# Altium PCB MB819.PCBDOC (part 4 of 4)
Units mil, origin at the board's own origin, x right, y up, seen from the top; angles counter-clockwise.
Board outline 4505 x 6805 mil, 4 copper layers (TopLayer, MidLayer1, GND, BottomLayer), stack 69.6 mil thick; 336 components, 282 nets, 1318 pads, 584 vias.
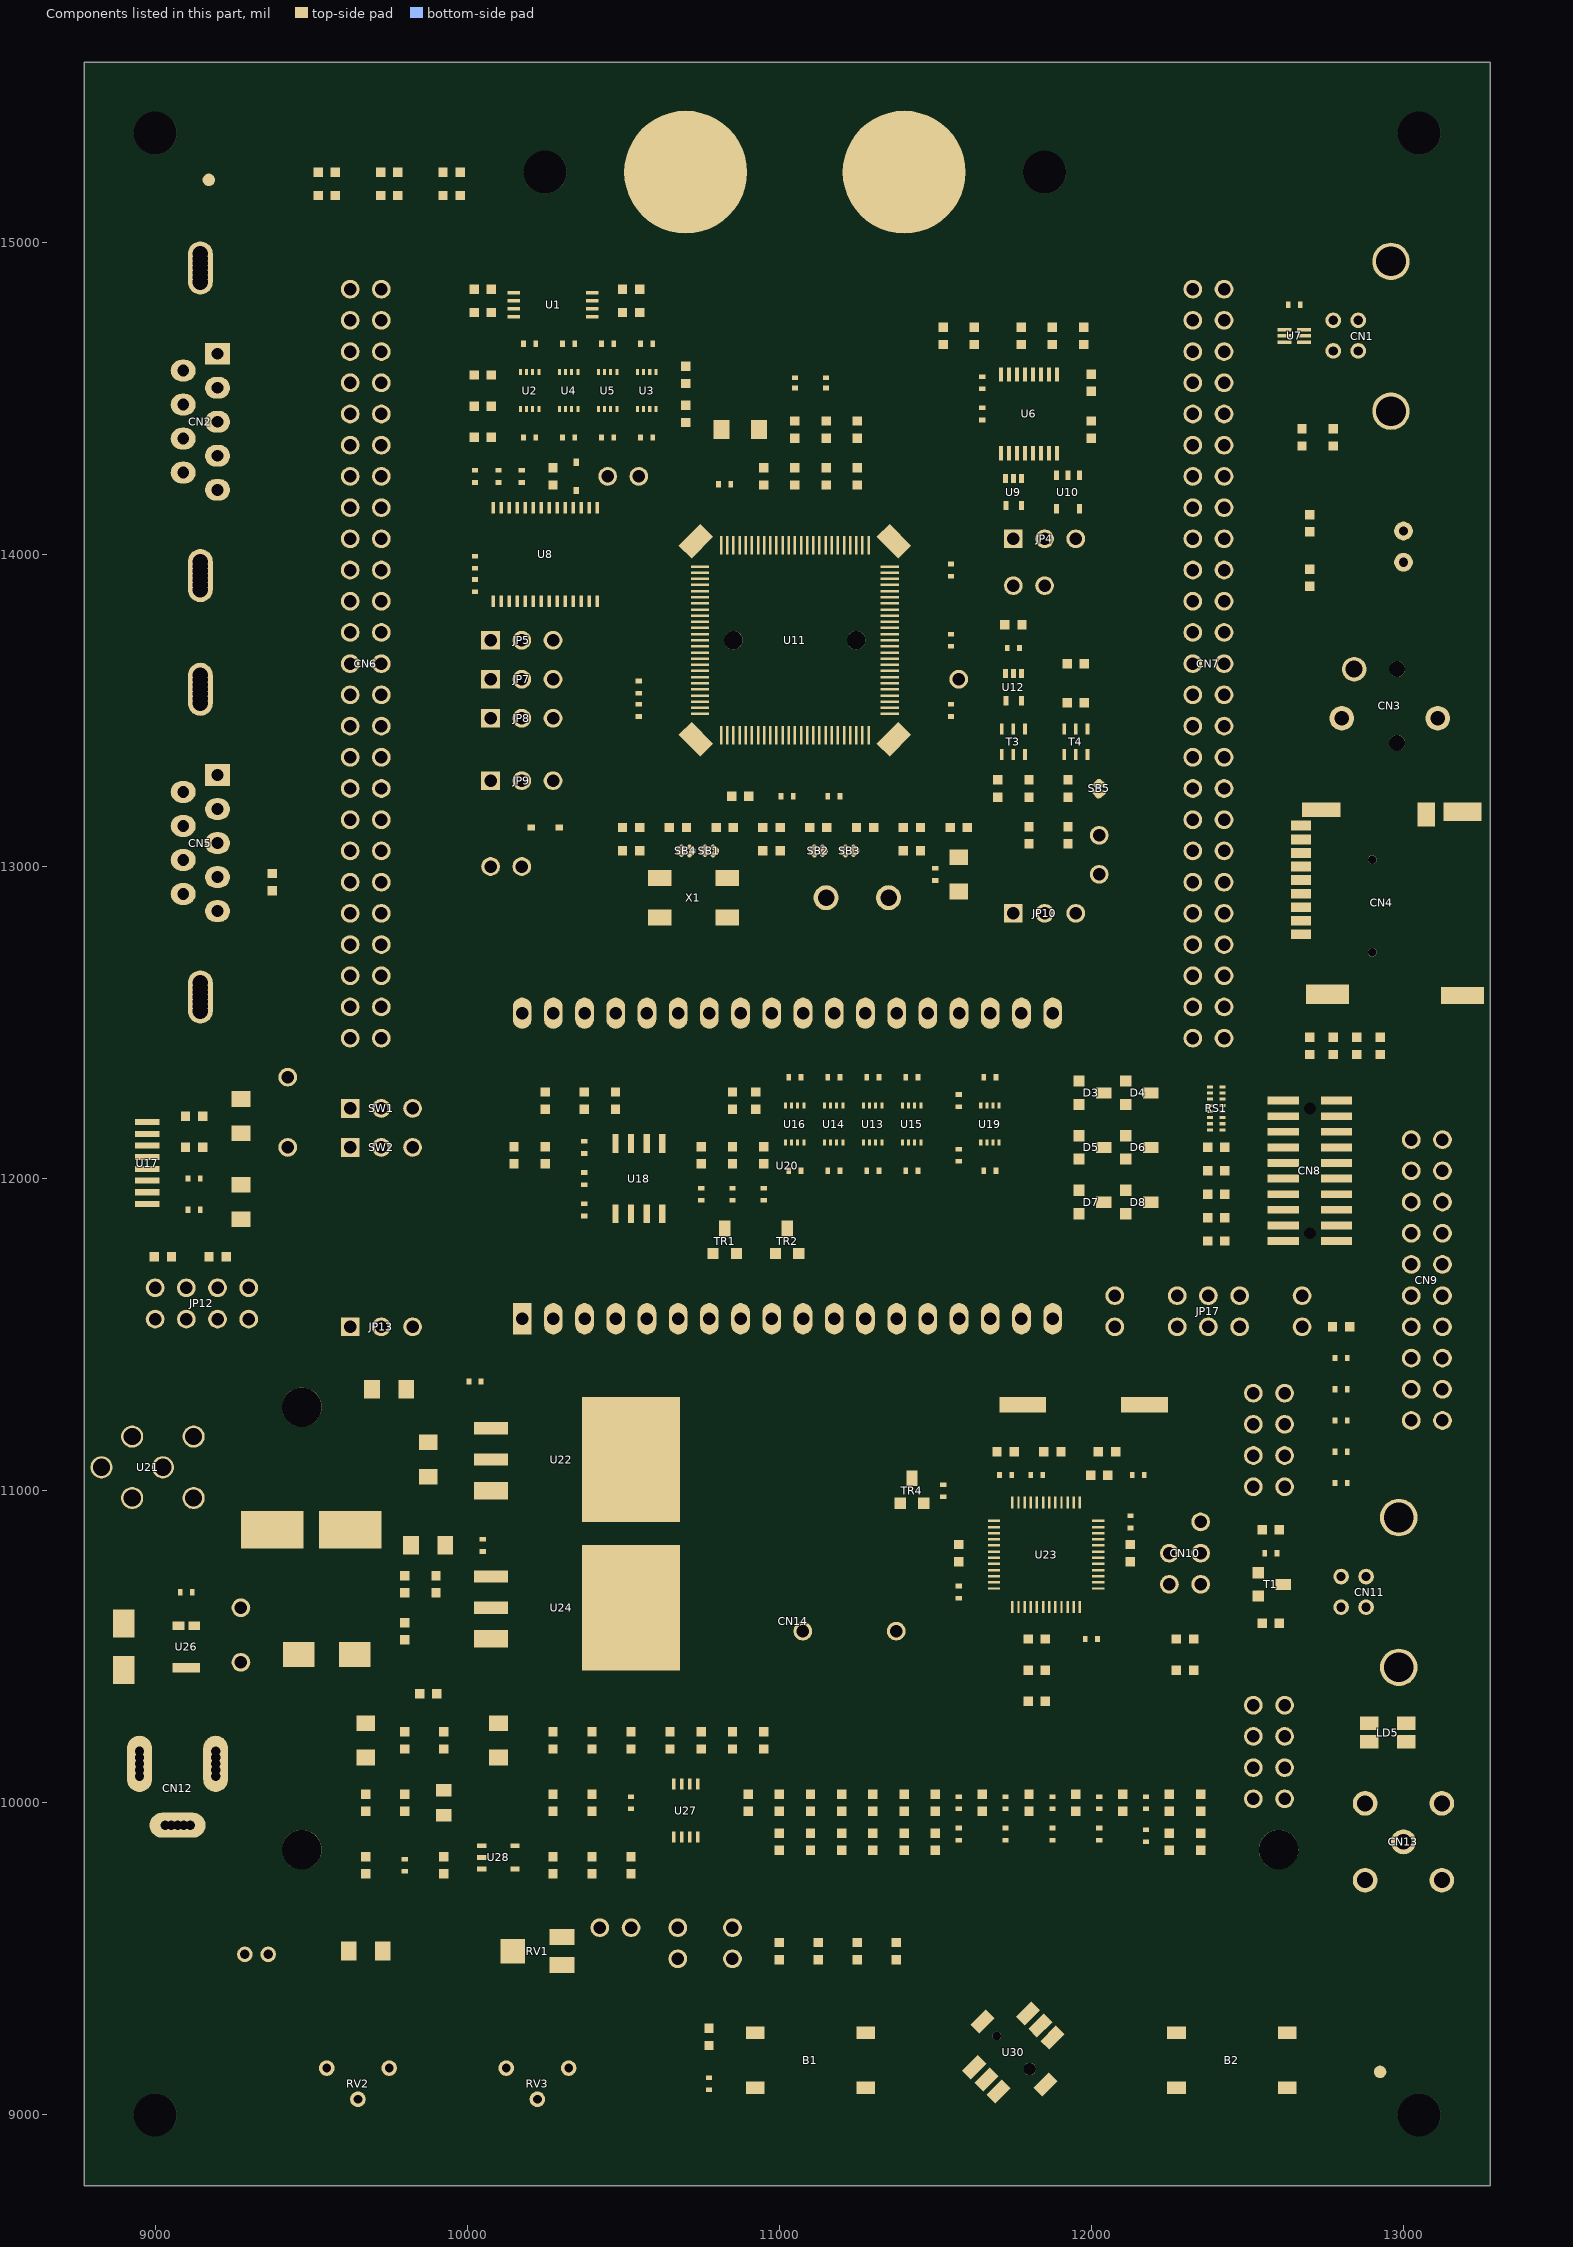
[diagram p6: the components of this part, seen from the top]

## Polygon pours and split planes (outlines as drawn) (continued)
D5V on BottomLayer (hatched 90Degree grid 10 track 10, remove dead copper): 9575,12550 9800,12550 9800,12700 10125,12700 10125,12465 9990,12465 9910,12385 9655,12385 9630,12410 9576.31,12410 9576.31,12550
GND on BottomLayer (hatched 90Degree grid 15 track 10, remove dead copper): 8775,8775 13275,8775 13275,15575 8775,15575

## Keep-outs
KeepOutLayer:
  lines w4: 12025,15125 12150,15125 ; 12025,15250 12150,15250 ; 12025,15375 12150,15375 ; 12275,15125 12275,15250 12275,15375 ; 12400,15125 12400,15250 12400,15375 ; 12525,15125 12525,15250 12525,15375 ; 12775,15250 12650,15250 ; 12150,15125 12150,15250 ; 12150,15125 12650,15125 ; 12150,15250 12650,15250 ; 12150,15250 12150,15375 ; 12150,15375 12650,15375 ; 12650,15125 12650,15250 ; 12650,15125 12775,15125 12775,15375 12650,15375 ; 12650,15250 12650,15375
  lines w5: 12025,15125 12025,15375 ; 8775,8775 8775,10233.87 8775,15575 13275,15575 13275,13155 ccw(c14448.78,12905.51) 13275,12656.01 13275,8775 8775,8775

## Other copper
TopLayer:
  text "1" at 12200,15275 h50
  text "B" at 12190,15165 h50
MidLayer1:
  text "2" at 12320,15275 h50
  text "B" at 12320,15165 h50
BottomLayer:
  text "4" at 12610,15275 h50
  text "B" at 12610,15165 h50
GND (plane layer: these items are gaps in the copper):
  rectangle: 12525,15100 12795,15400
  rectangle: 12400,15100 12525,15125
  rectangle: 12400,15375 12525,15400
  region: 12000,15400 12000,15100 12400,15100 12400,15400
  lines w4: 12025,15125 12150,15125 ; 12025,15250 12150,15250 ; 12025,15375 12150,15375 ; 12150,15255 12150,15250 ; 12275,15125 12275,15250 ; 12275,15255 12275,15375 ; 12400,15125 12400,15250 12400,15375 ; 12525,15125 12525,15250 12525,15375 ; 12150,15125 12650,15125 12650,15250 ; 12150,15125 12150,15250 ; 12150,15250 12650,15250 ; 12150,15250 12150,15375 ; 12150,15375 12650,15375 12650,15250
  lines w5: 12025,15125 12025,15375
  text "3" at 12485,15275 h50
  text "B" at 12485,15165 h50

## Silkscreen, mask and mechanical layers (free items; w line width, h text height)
TopOverlay:
  drawing of 7182 lines, arcs and shapes, not listed
  text "S" at 12070,15275 h50
  text "B" at 12075,15165 h50
  text "USB" at 13075,14955 h36
  text "GND" at 9425,14830 h36
  text "PC6" at 9795,14830 h36
  text "GND" at 12120,14830 h36
  text "PD15" at 12500,14830 h36
  text "PD13" at 12500,14740 h36
  text "PC7" at 9425,14730 h36
  text "PC8" at 9795,14730 h36
  text "PD14" at 12110,14730 h36
  text "PC9" at 9425,14630 h36
  text "PA8" at 9795,14630 h36
  text "PD12" at 12110,14630 h36
  text "PD11" at 12500,14625 h36
  text "PA10" at 9795,14540 h36
  text "PA9" at 9425,14535 h36
  text "PD10" at 12110,14530 h36
  text "PD9" at 12500,14530 h36
  text "GND" at 9795,14435 h36
  text "PA0" at 9425,14430 h36
  text "PC13" at 12110,14430 h36
  text "GND" at 12495,14430 h36
  text "PC14" at 9425,14335 h36
  text "PA11" at 9795,14330 h36
  text "RESET#" at 12085,14330 h36
  text "PD8" at 12500,14330 h36
  text "BL_Boot0" at 10495,14315 h36
  text "PA12" at 9425,14230 h36
  text "PA13" at 9795,14230 h36
  text "PB15" at 12120,14230 h36
  text "PB14" at 12500,14230 h36
  text "LDR" at 13067,14145 h36
  text "PC15" at 9425,14130 h36
  text "PA14" at 9795,14130 h36
  text "PB13" at 12120,14130 h36
  text "PB12" at 12500,14130 h36
  text "IDD" at 11892.77,14107.23 h36
  text "VDD" at 11745,14105 h36
  text "PC10" at 9425,14030 h36
  text "PC11" at 9795,14030 h36
  text "PB11" at 12120,14030 h36
  text "PB10" at 12500,14030 h36
  text "GND" at 9425,13930 h36
  text "PA15" at 9795,13930 h36
  text "PE15" at 12500,13930 h36
  text "D5V" at 12120,13925 h36
  text "IDD" at 11927.77,13872.23 h36
  text "PD0" at 9795,13835 h36
  text "PC12" at 9425,13830 h36
  text "PE14" at 12120,13830 h36
  text "PE13" at 12500,13830 h36
  text "IrDA" at 10026,13786 h36
  text "RS232" at 10203,13786 h36
  text "USART2" at 9070,13735 h36
  text "PH1" at 12500,13735 h36
  text "PD1" at 9425,13730 h36
  text "PD2" at 9795,13730 h36
  text "PH0" at 12120,13730 h36
  text "SPEAK" at 13015,13690 h36
  text "PD4" at 9795,13640 h36
  text "PD3" at 9425,13630 h36
  text "PE12" at 12120,13630 h36
  text "PE11" at 12500,13630 h36
  text "PD6" at 9795,13540 h36
  text "PD5" at 9425,13535 h36
  text "PE10" at 12120,13530 h36
  text "PE9" at 12500,13530 h36
  text "USART3" at 10385,13445 h36 r90
  text "GND" at 9795,13435 h36
  text "PD7" at 9425,13430 h36
  text "PE8" at 12115,13430 h36
  text "GND" at 12500,13430 h36
  text "BL_RESET" at 10216,13343 h36
  text "CTS" at 10024,13340 h36
  text "VLCD" at 9425,13330 h36
  text "PH2" at 9795,13330 h36
  text "PE7" at 12115,13330 h36
  text "PB2" at 12500,13330 h36
  text "Pin1" at 10590,13255 h36
  text "PB3" at 9425,13230 h36
  text "PB4" at 9795,13230 h36
  text "PB1" at 12115,13230 h36
  text "PB0" at 12500,13230 h36
  text "MSD" at 12945,13225 h36
  text "AIN5" at 12045,13160 h36
  text "PB5" at 9425,13130 h36
  text "PB6" at 9795,13130 h36
  text "PC4" at 12500,13130 h36
  text "PC5" at 12110,13105 h36
  text "PB7" at 9425,13030 h36
  text "PE0" at 9795,13030 h36
  text "PA7" at 12115,13030 h36
  text "PA6" at 12500,13030 h36
  text "GND" at 9425,12930 h36
  text "PE1" at 9795,12930 h36
  text "GND" at 12115,12930 h36
  text "PA5" at 12500,12930 h36
  text "GND" at 11870,12925 h36
  text "I2C_SMB" at 10030,12900 h36
  text "PE2" at 9425,12835 h36
  text "PE3" at 9795,12835 h36
  text "PA4" at 12115,12830 h36
  text "PA3" at 12500,12830 h36
  text "LDR" at 11720,12745 h36
  text "TRST" at 11875,12740 h36
  text "PE4" at 9425,12730 h36
  text "PE5" at 9795,12730 h36
  text "PA2" at 12120,12730 h36
  text "PA1" at 12500,12730 h36
  text "PB8" at 9425,12630 h36
  text "PB9" at 9795,12630 h36
  text "PC3" at 12115,12630 h36
  text "PC2" at 12500,12630 h36
  text "PE6" at 9425,12530 h36
  text "+3.3V" at 9795,12530 h36
  text "PC1" at 12115,12530 h36
  text "PC0" at 12500,12530 h36
  text "D5V" at 9425,12430 h36
  text "GND" at 9795,12430 h36
  text "PC13" at 12115,12430 h36
  text "GND" at 12500,12430 h36
  text "USART3" at 9070,12395 h36
  text "EXT JTAG" at 13010,12340 h36
  text "0" at 9610,12300 h36
  text "1" at 9820,12300 h36
  text "GND" at 9380,12235 h36
  text "Boot0" at 9950,12183 h36
  text "Boot1" at 9950,12063 h36
  text "5V" at 9397,12010 h36
  text "SW1" at 9400,11925 h35
  text "SW2" at 9510,11925 h35
  text "BOOT" at 9710,11925 h35
  text "X" at 9540,11855 h35
  text "User Flash" at 9665,11855 h35
  text "0" at 9425,11850 h35
  text "1" at 9425,11785 h35
  text "0" at 9540,11785 h35
  text "System memory" at 9665,11785 h35
  text "5V" at 9275,11735 h36
  text "1" at 9425,11720 h35
  text "1" at 9545,11720 h35
  text "SRAM" at 9665,11715 h35
  text "PB5" at 12215,11690 h36
  text "PB3" at 12325,11690 h36
  text "PB12" at 12450,11690 h36
  text "uSD" at 12625,11690 h36
  text "ADJ" at 9570,11605 h36
  text "3.3V" at 9780,11605 h36
  text "Audio OUT" at 12007,11470 h36 r90
  text "PSU" at 9015,11331 h36 r90
  text "USB" at 9220,11331 h36 r90
  text "board" at 9140,11300 h36 r90
  text "Daughter" at 9090,11280 h36 r90
  text "ST-LINK/V2" at 9325,11200 h36 r90
  text "3.3V" at 9230,10685 h36
  text "VDD" at 9240,10360 h36
  text "PSU 5V" at 9030,10325 h36
  text "ADJ" at 9245,10315 h36
  text "ST-LINK/V2" at 12750,10308 h36
  text "COM" at 13085,10173 h36
  text "DC5V" at 9143,9728 h40
  text "+" at 8878,9718 h40 r270
  text "-" at 9058,9713 h40 r270
  text "PA5(ADC IN5)" at 12880,9603 h36
  text "LED4" at 10789,9539 h36 r90
  text "LED3" at 10612,9535 h36 r90
  text "MIC" at 10450,9438 h36
BottomOverlay:
  drawing of 3267 lines, arcs and shapes, not listed
  text "B" at 12725,15275 h50
  text "B" at 12725,15165 h50
Mechanical1:
  lines w5: 13275,13145 13275,15575 8775,15575 8775,10233.87 8775,8775 13275,8775 13275,12655 cw(c14448.78,12904.49) 13275,13153.99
